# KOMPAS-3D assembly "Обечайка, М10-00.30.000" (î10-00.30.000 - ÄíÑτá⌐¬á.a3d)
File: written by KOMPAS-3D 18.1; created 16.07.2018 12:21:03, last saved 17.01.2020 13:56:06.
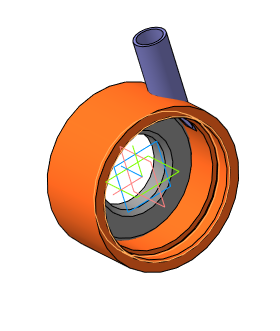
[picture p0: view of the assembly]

Document properties: Автор: Милов; Полное имя файла: C:\Users\User\Desktop\Магна 10 для Караби\М10-00.30.000 - Обечайка.a3d

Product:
- Part/product: Обечайка  | designation М10-00.30.000
    Материал: Полипропилен  ГОСТ 26996-86 (density 900 kg/m3)
    Масса: 0.647968
    source file: М10-00.30.000 - Обечайка.cdw
  - Component [detail]: Труба  | designation М10-00.30.003  | pos. 10  | Раздел спецификации: Детали; Форматы листов документа: A4; source file: М10-00.30.003 - Труба.cdw, М10-00.30.003 - Труба.m3d
  - Component [detail]: Стенка  | designation М10-00.30.001  | pos. 9  | Материал: Полипропилен  ГОСТ 26996-86 (density 900 kg/m3); Масса: 0.226956; Раздел спецификации: Детали; Форматы листов документа: A4; source file: М10-00.30.001 - Стенка.cdw, М10-00.30.001 - Стенка.m3d
  - Component [detail]: Обечайка  | designation М10-00.30.002  | pos. 8  | Масса: 0.421013; Раздел спецификации: Детали; Форматы листов документа: A4; source file: М10-00.30.002 - Обечайка.m3d
- Part/product: Обечайка  | designation М10-00.30.000  | pos. 0
    Материал: Полипропилен  ГОСТ 26996-86 (density 900 kg/m3)
    Масса: 0.782681
    Раздел спецификации: Сборочные единицы
    Форматы листов документа: A3
    source file: \\192.168.87.28\Konstructor_doc\Магна\Магна Ins\Магна ins 10\М10-00.00.000\3Д\М10-00.30.000 - Обечайка.cdw
  - Component [detail]: Труба ПВХ  | designation М13-01.30.003  | pos. 3  | Масса: 0.0162255; Раздел спецификации: Детали; Форматы листов документа: A4; Примечание: См. табл.; source file: ..\..\..\Магна ins 13\М13-01.00.000 ПВХ\Чертежи Компас\М13-01.30.003 - Труба.cdw, М10-00.30.003 - Труба.m3d
  - Component [detail]: Стенка ПВХ  | designation М10-10.30.001  | pos. 1  | Материал: Полипропилен  ГОСТ 26996-86 (density 0 kg/m3); Раздел спецификации: Детали; Форматы листов документа: A4; source file: М10-00.30.001 - Стенка.m3d
  - Component [detail]: Обечайка ПВХ  | designation М13-01.30.002  | pos. 2  | Масса: 0.766456; Раздел спецификации: Детали; Форматы листов документа: A4; Примечание: См. табл.; source file: ..\..\..\Магна ins 13\М13-01.00.000 ПВХ\Чертежи Компас\М13-01.30.002 - Обечайка.cdw, М10-00.30.002 - Обечайка.cdw, М10-00.30.002 - Обечайка.m3d

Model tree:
1. Эскиз:6  (with: Операция выдавливания:1)
2. Вырезать элемент выдавливания:5
     Расстояние 1 = 78
3. Эскиз:8  (with: Операция выдавливания:1)
4. Вырезать элемент выдавливания:6
     Расстояние 1 = 21
5. Эскиз:12  (with: Вырезать элемент выдавливания:6)
6. Вырезать элемент выдавливания:7
     Расстояние 2 = 4
7. Условное изображение резьбы:1  (with: Вырезать элемент выдавливания:6, Вырезать элемент выдавливания:7, Операция выдавливания:1)  (labels: M140x3; cil0_24705-2004 fine)
     Длина резьбы = 17; Шаг резьбы = 3; Номинальный диаметр резьбы = 140
8. Подгонка:1  (with: Вырезать элемент выдавливания:6)
9. Фаска:3  (with: Вырезать элемент выдавливания:6)
     Угол = 45; Длина 1 = 2; Длина 2 = 2
10. Сечение поверхностью:4  (with: Операция выдавливания:1, Вырезать элемент выдавливания:4, Плоскость под углом:1)  (labels: Полипропилен  ГОСТ 26996-86; Труба 32 PN10 S=2,9 FV PPR ф. "FV PLAST")
11. Эскиз:13  (with: Операция выдавливания:1)
12. Элемент выдавливания:1
     Расстояние 2 = 21
13. Эскиз:14  (with: Элемент выдавливания:1)
14. Элемент выдавливания:2
     Расстояние 1 = 4
15. Условное изображение резьбы:2  (with: Элемент выдавливания:1, Элемент выдавливания:2)  (labels: M140x4; cil0_24705-2004 fine)
     Длина резьбы = 17; Шаг резьбы = 4; Номинальный диаметр резьбы = 140
16. Подгонка:1  (with: Элемент выдавливания:1)
17. Фаска:2  (with: Элемент выдавливания:1, Эскиз:16)
     Угол = 45; Длина 1 = 2.5; Длина 2 = 2.5

Referenced files in C:\Users\User\Desktop\Магна 10 для Караби\: М10-00.30.002 - Обечайка.m3d, М10-00.30.001 - Стенка.m3d, М10-00.30.001 - Стенка.cdw, М10-00.30.003 - Труба.m3d, М10-00.30.003 - Труба.cdw, М10-00.30.002 - Обечайка.cdw
Referenced files in C:\Users\User\Desktop\Магна 10 для Караби\..\..\..\Магна ins 13\М13-01.00.000 ПВХ\Чертежи Компас\: М13-01.30.002 - Обечайка.cdw, М13-01.30.003 - Труба.cdw
Referenced files in \\192.168.87.28\Konstructor_doc\Магна\Магна Ins\Магна ins 10\М10-00.00.000\3Д\: М10-00.30.000 - Обечайка.cdw
Referenced files in D:\Magna\Магна Ins\Магна ins 10\М10-00.00.000\3Д\: М10-00.30.002 - Обечайка.m3d, М10-00.30.003 - Труба.m3d, М10-00.30.001 - Стенка.m3d
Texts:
  Body Specification ( left align )
  Body Specificaton ( centered )
  Точка начала. Х
  Точка начала. Y
  Точка начала. Z
  Труба 32 PN10 НПВХ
